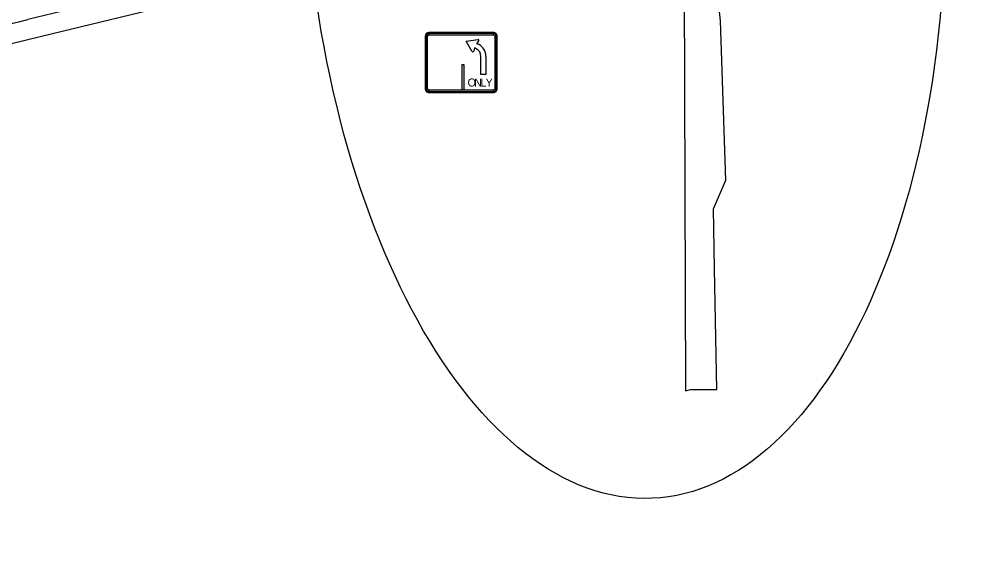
# Model space of a CAD drawing. Extents: x 2471014 to 2497726, y 6959577 to 6980268.
# Drawn here: x 2483804 to 2484597, y 6967084 to 6967525 of the extents above; entities that cross this region are included whole.
import ezdxf

# ---------------------------------------------------------------- set-up
doc = ezdxf.new("R2010")
doc.units = 0
for name, color, linetype in [('13', 7, 'Continuous'), ('18', 7, 'Continuous'), ('5', 7, 'Continuous'), ('C-FENC-BARR', 7, 'Continuous'), ('S-BRDG-BENT', 7, 'Continuous'), ('V7_50', 7, 'Continuous')]:
    doc.layers.add(name, color=color, linetype=linetype)

msp = doc.modelspace()

# ---------------------------------------------------------------- linework, layer by layer
at = {"layer": '13'}
msp.add_arc((2483135.77, 6970308.33), 2851, 278.31233, 283.64141, dxfattribs=at)
at = {"layer": '18'}
msp.add_line((2484139.68, 6967603.81), (2483811.46, 6967524.15), dxfattribs=at)
for centre, radius, start, end in [((2482619.39, 6971428.57), 4010, 282.00899, 287.31897), ((2483135.77, 6970308.33), 2865, 281.57278, 283.64141)]:
    msp.add_arc(centre, radius, start, end, dxfattribs=at)
at = {"layer": '5'}
msp.add_arc((2479474.04, 6969335.88), 8460, 6.37617, 6.37617, dxfattribs=at)
at = {"layer": 'C-FENC-BARR'}
for p, q in [((2484142.2, 6967510.35), (2484142.2, 6967466.6)), ((2484143.03, 6967510.35), (2484144.28, 6967510.35)), ((2484199.07, 6967513.47), (2484145.32, 6967513.47)), ((2484145.32, 6967511.39), (2484145.32, 6967512.64)), ((2484199.07, 6967512.64), (2484199.07, 6967511.39)), ((2484200.11, 6967510.35), (2484201.36, 6967510.35)), ((2484202.2, 6967466.6), (2484202.2, 6967510.35)), ((2484176.41, 6967506.18), (2484185.97, 6967507.63)), ((2484181.19, 6967497.78), (2484176.41, 6967506.18)), ((2484186.74, 6967506.28), (2484185.1, 6967504.28)), ((2484185.1, 6967504.28), (2484186.53, 6967503.59)), ((2484183.29, 6967500.54), (2484182.73, 6967498.01)), ((2484184.71, 6967499.85), (2484183.29, 6967500.54)), ((2484188.71, 6967478.47), (2484188.71, 6967493.48)), ((2484192.87, 6967493.48), (2484192.87, 6967478.47)), ((2484192.87, 6967478.47), (2484188.71, 6967478.47)), ((2484144.28, 6967466.6), (2484143.03, 6967466.6)), ((2484145.32, 6967464.31), (2484145.32, 6967465.56)), ((2484145.32, 6967463.47), (2484199.07, 6967463.47)), ((2484199.07, 6967465.56), (2484199.07, 6967464.31)), ((2484201.36, 6967466.6), (2484200.11, 6967466.6))]:
    msp.add_line(p, q, dxfattribs=at)
for points in [[(2484143.03, 6967510.35), (2484143.03, 6967466.6), (2484144.28, 6967466.6), (2484144.28, 6967510.35), (2484143.03, 6967510.35)], [(2484199.07, 6967512.64), (2484145.32, 6967512.64), (2484145.32, 6967511.39), (2484199.07, 6967511.39), (2484199.07, 6967512.64)], [(2484201.36, 6967466.6), (2484201.36, 6967510.35), (2484200.11, 6967510.35), (2484200.11, 6967466.6), (2484201.36, 6967466.6)], [(2484174.33, 6967486.81), (2484174.33, 6967465.56), (2484173.08, 6967465.56), (2484173.08, 6967486.81), (2484174.33, 6967486.81)], [(2484145.32, 6967464.31), (2484199.07, 6967464.31), (2484199.07, 6967465.56), (2484145.32, 6967465.56), (2484145.32, 6967464.31)]]:
    msp.add_lwpolyline(points, close=True, dxfattribs=at)
for centre, radius, start, end in [((2484145.32, 6967510.35), 3.12, 90.00021, 179.99985), ((2484145.32, 6967510.35), 2.29, 90.00021, 179.99985), ((2484145.32, 6967510.35), 1.04, 90.00021, 179.99985), ((2484199.07, 6967510.35), 3.12, 0, 90.00021), ((2484199.07, 6967510.35), 2.29, 0, 90.00021), ((2484199.07, 6967510.35), 1.04, 0, 90.00021), ((2484186.1, 6967506.81), 0.833, 320.71198, 98.68136), ((2484181.62, 6967493.48), 11.24, 0.00027, 64.13545), ((2484181.92, 6967498.19), 0.833, 209.61489, 347.63183), ((2484181.62, 6967493.48), 7.08, 0.00027, 64.13545), ((2484145.32, 6967466.6), 3.12, 179.99985, 270.00006), ((2484145.32, 6967466.6), 2.29, 179.99985, 270.00006), ((2484145.32, 6967466.6), 1.04, 179.99985, 270.00006), ((2484199.07, 6967466.6), 3.12, 270.00006, 0.00027), ((2484199.07, 6967466.6), 2.29, 270.00006, 0.00027), ((2484199.07, 6967466.6), 1.04, 270.00006, 0.00027)]:
    msp.add_arc(centre, radius, start, end, dxfattribs=at)
at = {"layer": 'S-BRDG-BENT'}
msp.add_arc((2480975.49, 6978806.4), 11476, 278.540166, 284.374936, dxfattribs=at)
at = {"layer": 'V7_50'}
msp.add_lwpolyline([(2483270.89, 6967411.98), (2483478.09, 6967446.69), (2483743.04, 6967491.08), (2483822.84, 6967510.45), (2484088.03, 6967574.81), (2484175.49, 6967596.03), (2484243.52, 6967612.54), (2484257.54, 6967597.42), (2484258.29, 6967560.02), (2484258.47, 6967550.85), (2484357.78, 6967551.14), (2484359.02, 6967215.32), (2484363.23, 6967216.39), (2484385.19, 6967216.41), (2484383.19, 6967316.75), (2484382.18, 6967366.74), (2484392.7, 6967390.4), (2484388.08, 6967523.27), (2484376.95, 6967628), (2484375.63, 6967693.89), (2484447.6, 6967710.17), (2484746.88, 6967763.8)], dxfattribs=at)
msp.add_ellipse((2484308.07, 6967658.79), major_axis=(23.18, -533), ratio=0.5, dxfattribs=at)

# ---------------------------------------------------------------- texts
at = {"layer": 'C-FENC-BARR'}
for s, p in [('O', (2484177.56, 6967468.47)), ('N', (2484183.03, 6967468.47)), ('L', (2484188.29, 6967468.47)), ('Y', (2484192.56, 6967468.47))]:
    msp.add_text(s, height=6.67, dxfattribs=at).set_placement(p)

doc.saveas('drawing.dxf')
